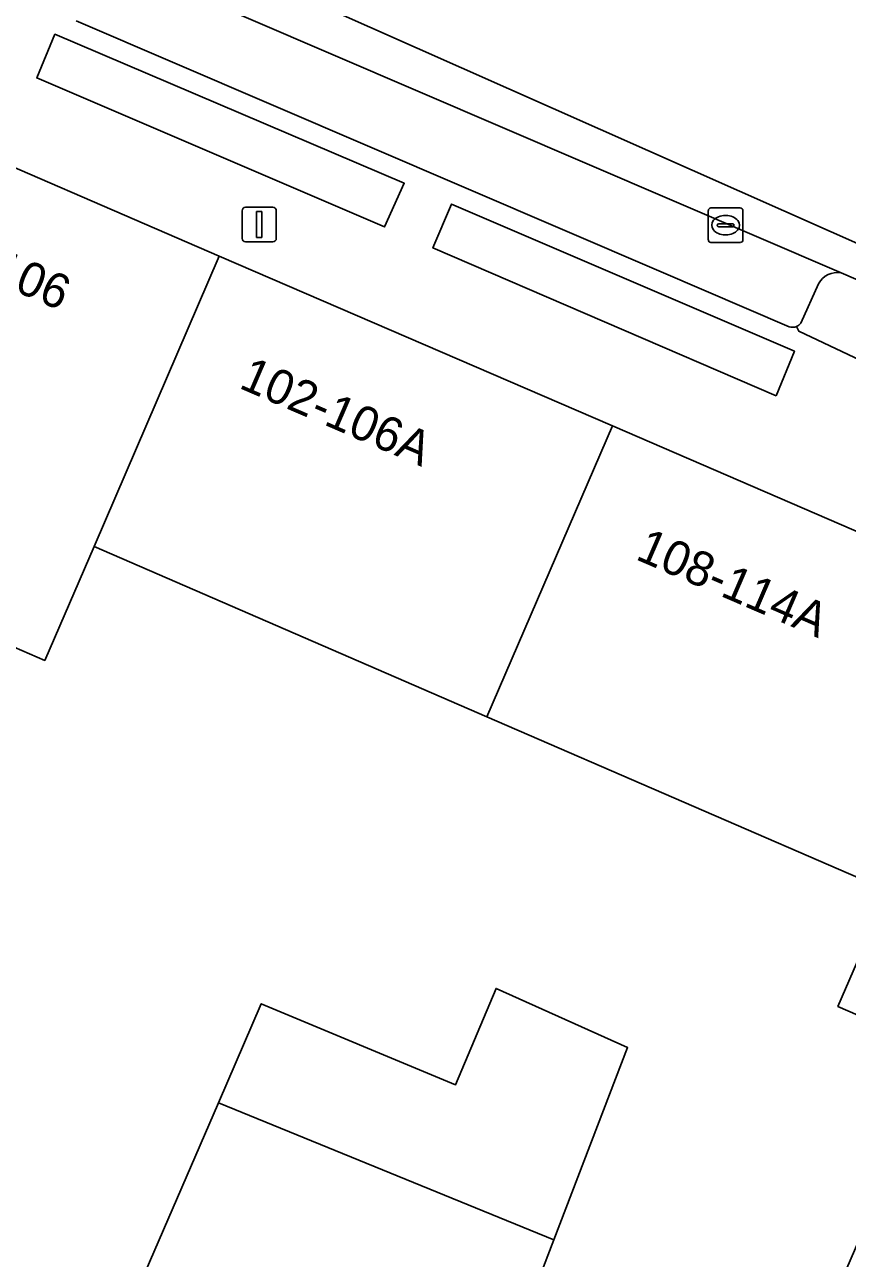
# Model space of a CAD drawing. Extents: x 161798 to 162385, y 382315 to 382833.
# Drawn here: x 162212.1 to 162235.92, y 382589.12 to 382624.82 of the extents above; entities that cross this region are included whole.
import ezdxf

# ---------------------------------------------------------------- set-up
doc = ezdxf.new("R2010")
doc.units = 0
for name, color, linetype in [('IMGEO_Erf', 7, 'Continuous'), ('IMGEO_Groenvoorziening', 7, 'Continuous'), ('IMGEO_Kolk', 7, 'Continuous'), ('IMGEO_Lichtmast', 7, 'Continuous'), ('IMGEO_Pand', 7, 'Continuous'), ('IMGEO_Pand_nummerreeks', 7, 'Continuous'), ('IMGEO_Parkeervlak_open', 7, 'Continuous'), ('IMGEO_Rijbaan_lokaal_gesloten', 7, 'Continuous'), ('IMGEO_Voetpad_open', 7, 'Continuous')]:
    doc.layers.add(name, color=color, linetype=linetype)

msp = doc.modelspace()

# ---------------------------------------------------------------- linework, layer by layer
at = {"layer": 'IMGEO_Erf'}
for points in [[(162236.893, 382599.851), (162225.486, 382604.794), (162214.108, 382609.725), (162212.678, 382606.426), (162208.675, 382608.161)], [(162239.564, 382579.067), (162230.156, 382575.563), (162238.632, 382595.119), (162235.65, 382596.412), (162237.101, 382599.761)]]:
    msp.add_lwpolyline(points, dxfattribs=at)
msp.add_lwpolyline([(162220.802, 382574.936), (162218.113, 382575.994), (162220.912, 382582.668), (162214.119, 382585.338), (162217.707, 382593.617), (162218.951, 382596.487), (162224.575, 382594.142), (162225.75, 382596.93), (162229.557, 382595.219), (162227.423, 382589.653), (162224.244, 382581.359), (162223.602, 382581.611)], close=True, dxfattribs=at)
at = {"layer": 'IMGEO_Groenvoorziening'}
for points in [[(162222.519, 382618.968), (162223.092, 382620.232), (162212.974, 382624.543), (162212.448, 382623.284)], [(162233.864, 382614.081), (162234.387, 382615.372), (162224.459, 382619.631), (162223.921, 382618.362)]]:
    msp.add_lwpolyline(points, close=True, dxfattribs=at)
for points in [[(162238.442, 382616.477), (162235.739, 382617.639)], [(162235.09, 382617.324), (162234.576, 382616.185)], [(162234.45, 382616.089), (162234.516, 382615.954), (162237.909, 382614.355), (162238.222, 382614.486)]]:
    msp.add_lwpolyline(points, dxfattribs=at)
for centre, radius, start, end in [((162235.629, 382617.039), 0.61, 79.6112, 152.1692), ((162234.326, 382616.383), 0.319, 292.9123, 321.6956)]:
    msp.add_arc(centre, radius, start, end, dxfattribs=at)
at = {"layer": 'IMGEO_Kolk'}
for p, q in [((162231.896, 382618.593), (162231.896, 382619.445)), ((162231.971, 382619.519), (162232.823, 382619.519)), ((162232.897, 382619.445), (162232.897, 382618.593)), ((162232.155, 382619.013), (162232.155, 382619.025)), ((162232.593, 382618.976), (162232.195, 382618.976)), ((162232.198, 382619.062), (162232.596, 382619.062)), ((162232.384, 382619.299), (162232.409, 382619.299)), ((162232.639, 382619.025), (162232.639, 382619.013)), ((162232.407, 382618.739), (162232.382, 382618.739)), ((162232.823, 382618.519), (162231.971, 382618.519))]:
    msp.add_line(p, q, dxfattribs=at)
for points in [[(162231.896, 382618.593), (162231.896, 382619.445)], [(162231.971, 382619.519), (162232.823, 382619.519)], [(162232.897, 382619.445), (162232.897, 382618.593)], [(162232.823, 382618.519), (162231.971, 382618.519)]]:
    msp.add_lwpolyline(points, dxfattribs=at)
for centre, radius, start, end in [((162231.973, 382619.443), 0.0765, 91.552, 178.448), ((162231.973, 382619.443), 0.0765, 91.552, 178.448), ((162232.821, 382619.443), 0.0765, 1.552, 88.448), ((162232.821, 382619.443), 0.0765, 1.552, 88.448), ((162232.195, 382619.022), 0.0403, 85.8775, 175.7526), ((162232.192, 382619.012), 0.0366, 178.938, 274.7102), ((162232.596, 382619.019), 0.043, 264.8664, 352.4533), ((162232.6, 382619.024), 0.0386, 1.7309, 96.639), ((162231.973, 382618.595), 0.0765, 181.552, 268.448), ((162231.973, 382618.595), 0.0765, 181.552, 268.448), ((162232.821, 382618.595), 0.0765, 271.552, 358.448), ((162232.821, 382618.595), 0.0765, 271.552, 358.448)]:
    msp.add_arc(centre, radius, start, end, dxfattribs=at)
for centre, major_axis, ratio, start_param, end_param in [((162232.383, 382619.019), (-0.387, 0.002), 0.722429, 4.712389, 7.853982), ((162232.408, 382619.019), (-0.39, 0.002), 0.717154, 1.570796, 4.712389)]:
    msp.add_ellipse(centre, major_axis=major_axis, ratio=ratio, start_param=start_param, end_param=end_param, dxfattribs=at)
at = {"layer": 'IMGEO_Lichtmast'}
for p, q in [((162218.395, 382618.639), (162218.395, 382619.439)), ((162218.395, 382619.439), (162218.395, 382618.639)), ((162218.495, 382619.539), (162219.285, 382619.539)), ((162219.285, 382619.539), (162218.495, 382619.539)), ((162219.385, 382619.439), (162219.385, 382618.639)), ((162219.385, 382618.639), (162219.385, 382619.439)), ((162219.285, 382618.539), (162218.495, 382618.539)), ((162218.495, 382618.539), (162219.285, 382618.539))]:
    msp.add_line(p, q, dxfattribs=at)
msp.add_lwpolyline([(162218.815, 382619.414), (162218.965, 382619.414), (162218.965, 382618.664), (162218.815, 382618.664), (162218.815, 382619.414)], dxfattribs=at)
for centre, start, end in [((162218.495, 382619.439), 90, 180), ((162218.495, 382619.439), 90, 180), ((162219.285, 382619.439), 0, 90), ((162219.285, 382619.439), 360, 90), ((162218.495, 382618.639), 180, 270), ((162218.495, 382618.639), 180, 270), ((162219.285, 382618.639), 270, 0), ((162219.285, 382618.639), 270, 0)]:
    msp.add_arc(centre, 0.1, start, end, dxfattribs=at)
at = {"layer": 'IMGEO_Pand'}
for points in [[(162214.108, 382609.725), (162217.734, 382618.126), (162208.854, 382621.959), (162204.087, 382610.149), (162208.675, 382608.161), (162212.678, 382606.426)], [(162225.486, 382604.794), (162229.119, 382613.211), (162217.734, 382618.126), (162214.108, 382609.725)], [(162225.486, 382604.794), (162236.893, 382599.851), (162240.534, 382608.284), (162229.119, 382613.211)], [(162240.534, 382608.284), (162236.893, 382599.851), (162237.101, 382599.761), (162235.65, 382596.412), (162238.632, 382595.119), (162230.156, 382575.563), (162239.564, 382579.067), (162245.276, 382592.24), (162246.707, 382595.54), (162246.525, 382595.619), (162250.193, 382604.115)], [(162217.707, 382593.617), (162227.423, 382589.653), (162229.557, 382595.219), (162225.75, 382596.93), (162224.575, 382594.142), (162218.951, 382596.487)], [(162223.602, 382581.611), (162224.244, 382581.359), (162227.423, 382589.653), (162217.707, 382593.617), (162214.119, 382585.338), (162220.912, 382582.668)]]:
    msp.add_lwpolyline(points, close=True, dxfattribs=at)
at = {"layer": 'IMGEO_Parkeervlak_open'}
for points in [[(162235.739, 382617.639), (162213.679, 382627.112)], [(162213.588, 382624.937), (162230.532, 382617.668), (162234.242, 382616.077)], [(162234.576, 382616.185), (162235.09, 382617.324)]]:
    msp.add_lwpolyline(points, dxfattribs=at)
for centre, radius, start, end in [((162235.629, 382617.039), 0.61, 79.6112, 152.1692), ((162234.326, 382616.383), 0.319, 292.9123, 321.6956), ((162234.329, 382616.374), 0.31, 253.6656, 292.9381)]:
    msp.add_arc(centre, radius, start, end, dxfattribs=at)
at = {"layer": 'IMGEO_Rijbaan_lokaal_gesloten'}
msp.add_lwpolyline([(162284.329, 382598.88), (162252.839, 382611.116), (162211.378, 382629.505), (162210.854, 382628.309), (162211.464, 382628.073), (162213.679, 382627.112), (162235.739, 382617.639), (162238.442, 382616.477), (162255.911, 382608.99), (162257.528, 382608.307), (162269.376, 382603.243), (162271.017, 382602.539), (162288.503, 382595.016), (162290.216, 382594.295), (162295.8, 382591.876), (162295.848, 382591.854)], dxfattribs=at)
at = {"layer": 'IMGEO_Voetpad_open'}
for points in [[(162202.347, 382625.528), (162202.052, 382624.786), (162208.854, 382621.959), (162217.734, 382618.126), (162229.119, 382613.211), (162240.534, 382608.284), (162250.193, 382604.115), (162262.061, 382598.95), (162264.942, 382597.806), (162288.531, 382587.678)], [(162234.242, 382616.077), (162230.532, 382617.668), (162213.588, 382624.937)], [(162238.222, 382614.486), (162237.909, 382614.355), (162234.516, 382615.954), (162234.45, 382616.089)]]:
    msp.add_lwpolyline(points, dxfattribs=at)
for points in [[(162212.448, 382623.284), (162212.974, 382624.543), (162223.092, 382620.232), (162222.519, 382618.968)], [(162233.864, 382614.081), (162223.921, 382618.362), (162224.459, 382619.631), (162234.387, 382615.372)]]:
    msp.add_lwpolyline(points, close=True, dxfattribs=at)
msp.add_arc((162234.329, 382616.374), 0.31, 253.6656, 292.9381, dxfattribs=at)

# ---------------------------------------------------------------- texts
at = {"layer": 'IMGEO_Pand_nummerreeks'}
for s, p in [('100-106', (162208.628, 382618.484)), ('102-106A', (162218.271, 382614.322)), ('108-114A', (162229.755, 382609.364))]:
    msp.add_text(s, height=1, rotation=336.6521, dxfattribs=at).set_placement(p)

doc.saveas('drawing.dxf')
